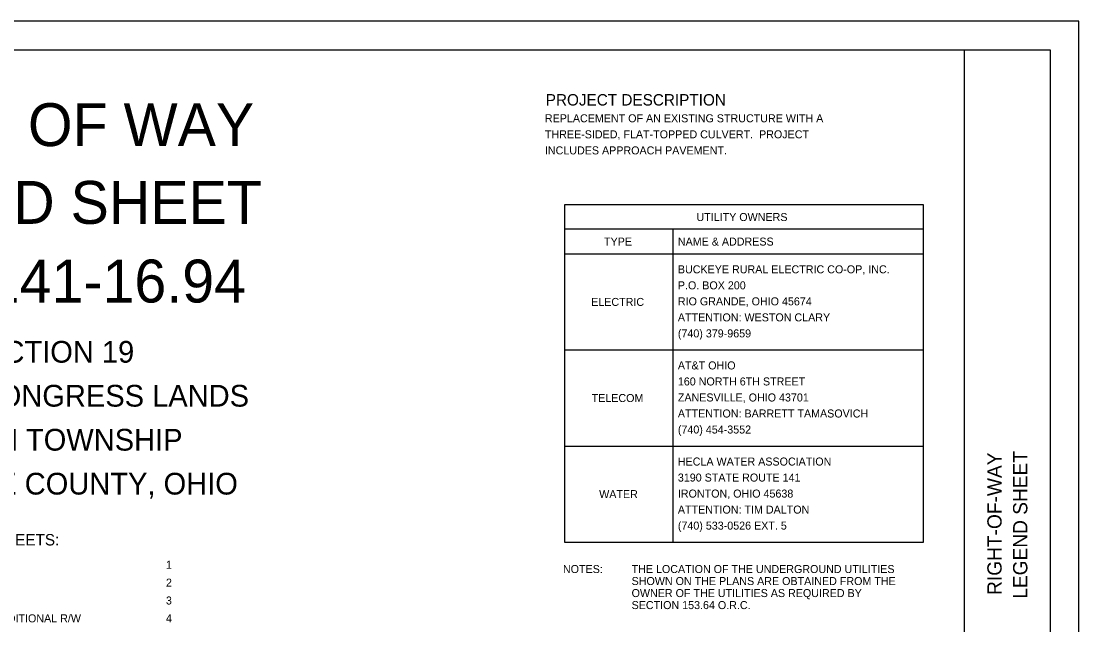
# Model space of a CAD drawing. Extents: x 0 to 34, y 0 to 22.
# Drawn here: x 15.51 to 34, y 11.45 to 22 of the extents above; entities that cross this region are included whole.
import ezdxf

# ---------------------------------------------------------------- set-up
doc = ezdxf.new("R2010")
doc.units = 0
for name, color, linetype in [('SH_Border', 7, 'Continuous'), ('SH_Cut_Line', 7, 'Continuous'), ('SH_Data', 7, 'Continuous'), ('SH_Text', 7, 'Continuous')]:
    doc.layers.add(name, color=color, linetype=linetype)

msp = doc.modelspace()

# ---------------------------------------------------------------- linework, layer by layer
at = {"layer": 'SH_Border'}
msp.add_line((32, 0.5), (32, 21.5), dxfattribs=at)
msp.add_lwpolyline([(1.5, 21.5), (33.5, 21.5), (33.5, 0.5), (1.5, 0.5)], close=True, dxfattribs=at)
at = {"layer": 'SH_Cut_Line'}
msp.add_lwpolyline([(0, 0), (34, 0), (34, 22), (0, 22)], close=True, dxfattribs=at)
at = {"layer": 'SH_Text'}
for p, q in [((31.281, 18.362), (25.007, 18.362)), ((26.909, 12.892), (26.909, 18.362)), ((25.007, 17.932), (31.281, 17.932)), ((25.007, 16.252), (31.281, 16.252)), ((25.007, 14.572), (31.281, 14.572))]:
    msp.add_line(p, q, dxfattribs=at)
msp.add_lwpolyline([(25.007, 12.892), (31.281, 12.892), (31.281, 18.791), (25.007, 18.791)], close=True, dxfattribs=at)

# ---------------------------------------------------------------- texts
at = {"layer": 'SH_Data'}
for s, height, p in [('RIGHT OF WAY', 0.75, (12.227, 19.816)), ('LEGEND SHEET', 0.75, (11.968, 18.457)), ('LAW-141-16.94', 0.75, (12.414, 17.082)), ('SECTION 19', 0.38, (14.519, 16.03)), ('T-3, R-16, CONGRESS LANDS', 0.38, (12.319, 15.262)), ('MASON TOWNSHIP', 0.38, (13.586, 14.493)), ('LAWRENCE COUNTY, OHIO', 0.38, (12.548, 13.725)), ('INDEX OF SHEETS:', 0.2, (13.692, 12.835)), ('1', 0.14, (18.038, 12.427)), ('2', 0.14, (18.038, 12.115)), ('3', 0.14, (18.038, 11.803)), ('SUMMARY OF ADDITIONAL R/W', 0.14, (13.692, 11.491)), ('4', 0.14, (18.038, 11.491))]:
    msp.add_text(s, height=height, dxfattribs=at).set_placement(p)
for s, p in [('RIGHT-OF-WAY', (32.65, 11.971)), ('LEGEND SHEET', (33.1, 11.904))]:
    msp.add_text(s, height=0.25, rotation=90, dxfattribs=at).set_placement(p)
at = {"layer": 'SH_Text'}
for s, height, p in [('PROJECT DESCRIPTION', 0.2, (24.679, 20.525)), ('REPLACEMENT OF AN EXISTING STRUCTURE WITH A', 0.14, (24.664, 20.232)), ('THREE-SIDED, FLAT-TOPPED CULVERT.  PROJECT', 0.14, (24.664, 19.952)), ('INCLUDES APPROACH PAVEMENT.', 0.14, (24.664, 19.671)), ('UTILITY OWNERS', 0.14, (27.314, 18.506)), ('TYPE', 0.14, (25.698, 18.077)), ('NAME & ADDRESS', 0.14, (26.989, 18.077)), ('BUCKEYE RURAL ELECTRIC CO-OP, INC.', 0.14, (26.989, 17.592)), ('P.O. BOX 200', 0.14, (26.989, 17.312)), ('ELECTRIC', 0.14, (25.473, 17.022)), ('RIO GRANDE, OHIO 45674', 0.14, (26.989, 17.032)), ('ATTENTION: WESTON CLARY', 0.14, (26.989, 16.752)), ('(740) 379-9659', 0.14, (26.989, 16.472)), ('AT&T OHIO', 0.14, (26.989, 15.912)), ('160 NORTH 6TH STREET', 0.14, (26.989, 15.632)), ('TELECOM', 0.14, (25.481, 15.342)), ('ZANESVILLE, OHIO 43701', 0.14, (26.989, 15.352)), ('ATTENTION: BARRETT TAMASOVICH', 0.14, (26.989, 15.072)), ('(740) 454-3552', 0.14, (26.989, 14.792)), ('HECLA WATER ASSOCIATION', 0.14, (26.989, 14.232)), ('3190 STATE ROUTE 141', 0.14, (26.989, 13.952)), ('WATER', 0.14, (25.613, 13.662)), ('IRONTON, OHIO 45638', 0.14, (26.989, 13.672)), ('ATTENTION: TIM DALTON', 0.14, (26.989, 13.392)), ('(740) 533-0526 EXT. 5', 0.14, (26.989, 13.112)), ('NOTES:', 0.14, (24.98, 12.353)), ('THE LOCATION OF THE UNDERGROUND UTILITIES', 0.14, (26.18, 12.353)), ('SHOWN ON THE PLANS ARE OBTAINED FROM THE', 0.14, (26.18, 12.143)), ('OWNER OF THE UTILITIES AS REQUIRED BY', 0.14, (26.18, 11.933)), ('SECTION 153.64 O.R.C.', 0.14, (26.18, 11.723))]:
    msp.add_text(s, height=height, dxfattribs=at).set_placement(p)

doc.saveas('drawing.dxf')
